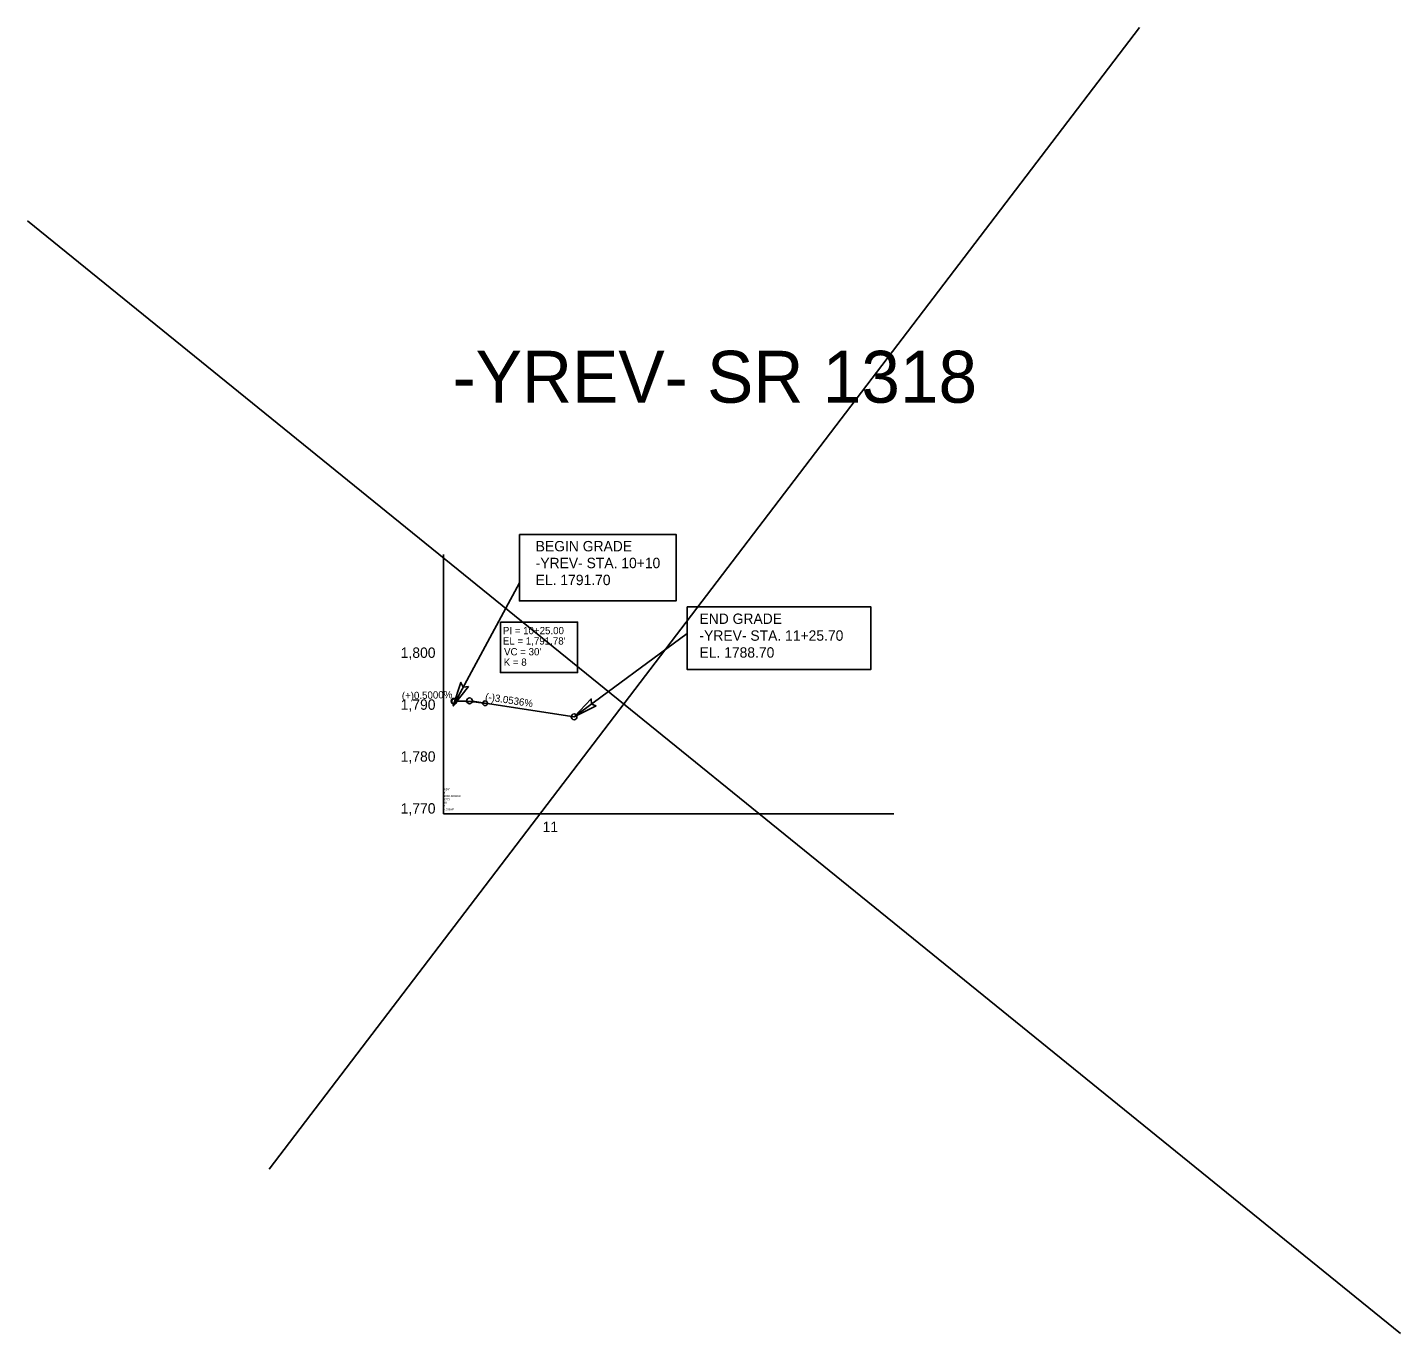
# Model space of a CAD drawing. Extents: x 572269 to 579912, y -56875 to -49627.
# Drawn here: x 578589 to 579912, y -53135 to -51877 of the extents above; entities that cross this region are included whole.
import ezdxf

# ---------------------------------------------------------------- set-up
doc = ezdxf.new("R2010")
doc.units = 0
for name, color, linetype in [('COGO Default Spiral', 7, 'Continuous'), ('Exist Profile Cell', 7, 'Continuous'), ('Exist Vertical Profile Ground Line', 7, 'Continuous'), ('Exist Vertical Profile Horizontal Axis Label Major', 7, 'Continuous'), ('Exist Vertical Profile Vertical Axis Label', 7, 'Continuous'), ('Prop Grid Mask', 7, 'Continuous'), ('Prop PFL Text', 7, 'Continuous'), ('Prop Vertical Profile Curve Label', 7, 'Continuous'), ('Prop Vertical Profile Grade', 7, 'Continuous'), ('Prop Vertical Profile Grade Label', 7, 'Continuous'), ('Prop VPI Label', 7, 'Continuous'), ('Typical Terminator CELL', 7, 'Continuous')]:
    doc.layers.add(name, color=color, linetype=linetype)

# ---------------------------------------------------------------- blocks, each defined once
blk = doc.blocks.new('TERMINATOR')
at = {"layer": 'Typical Terminator CELL'}
blk.add_lwpolyline([(-0.469, 0.081), (0, 0), (-0.471, -0.083), (-0.411, 0)], close=True, dxfattribs=at)

msp = doc.modelspace()

# ---------------------------------------------------------------- linework, layer by layer
at = {"layer": 'COGO Default Spiral'}
for p, q in [((579660.3, -51876.6), (578821.8, -52976.3)), ((578588.9, -52063), (579911.8, -53134.7))]:
    msp.add_line(p, q, dxfattribs=at)
at = {"layer": 'Exist Profile Cell'}
for q in [(578989.9, -52384.2), (579423.8, -52634.2), (578989.9, -52634.2)]:
    msp.add_line((578989.9, -52634.2), q, dxfattribs=at)
at = {"layer": 'Exist Vertical Profile Ground Line'}
msp.add_line((579029.9, -52527.6), (579115.6, -52540.7), dxfattribs=at)
msp.add_spline([(578999.9, -52525.7), (579000.5, -52525.6), (579001.1, -52525.6), (579001.7, -52525.6), (579002.3, -52525.6), (579002.9, -52525.6), (579003.5, -52525.6), (579004.1, -52525.6), (579004.7, -52525.6), (579005.3, -52525.6), (579005.9, -52525.6), (579006.5, -52525.6), (579007.1, -52525.6), (579007.7, -52525.6), (579008.3, -52525.7), (579008.9, -52525.7), (579009.5, -52525.7), (579010.1, -52525.7), (579010.7, -52525.7), (579011.3, -52525.8), (579011.9, -52525.8), (579012.5, -52525.8), (579013.1, -52525.8), (579013.7, -52525.9), (579014.3, -52525.9), (579014.9, -52525.9), (579015.5, -52526), (579016.1, -52526), (579016.7, -52526.1), (579017.3, -52526.1), (579017.9, -52526.2), (579018.5, -52526.2), (579019.1, -52526.3), (579019.7, -52526.3), (579020.3, -52526.4), (579020.9, -52526.4), (579021.5, -52526.5), (579022.1, -52526.6), (579022.7, -52526.6), (579023.3, -52526.7), (579023.9, -52526.8), (579024.5, -52526.8), (579025.1, -52526.9), (579025.7, -52527), (579026.3, -52527.1), (579026.9, -52527.1), (579027.5, -52527.2), (579028.1, -52527.3), (579028.7, -52527.4), (579029.3, -52527.5), (579029.9, -52527.6)], degree=3, dxfattribs=at)
at = {"layer": 'Prop Grid Mask'}
for points in [[(579062.9, -52364.9), (579213.9, -52364.9), (579213.9, -52429), (579062.9, -52429)], [(579224.7, -52434.6), (579401.4, -52434.6), (579401.4, -52495.2), (579224.7, -52495.2)], [(579044.6, -52449.4), (579119, -52449.4), (579119, -52498), (579044.6, -52498)]]:
    msp.add_lwpolyline(points, close=True, dxfattribs=at)
at = {"layer": 'Prop PFL Text'}
for p, q in [((578999.1, -52530.2), (579062.9, -52411.6)), ((579115.6, -52540.7), (579224.7, -52460.5))]:
    msp.add_line(p, q, dxfattribs=at)
at = {"layer": 'Prop Vertical Profile Curve Label'}
for centre in [(578999.9, -52525.7), (579029.9, -52527.6)]:
    msp.add_circle(centre, 2.25, dxfattribs=at)
at = {"layer": 'Prop Vertical Profile Grade'}
msp.add_line((579029.9, -52527.6), (579115.6, -52540.7), dxfattribs=at)
msp.add_spline([(578999.9, -52525.7), (579000.5, -52525.6), (579001.1, -52525.6), (579001.7, -52525.6), (579002.3, -52525.6), (579002.9, -52525.6), (579003.5, -52525.6), (579004.1, -52525.6), (579004.7, -52525.6), (579005.3, -52525.6), (579005.9, -52525.6), (579006.5, -52525.6), (579007.1, -52525.6), (579007.7, -52525.6), (579008.3, -52525.7), (579008.9, -52525.7), (579009.5, -52525.7), (579010.1, -52525.7), (579010.7, -52525.7), (579011.3, -52525.8), (579011.9, -52525.8), (579012.5, -52525.8), (579013.1, -52525.8), (579013.7, -52525.9), (579014.3, -52525.9), (579014.9, -52525.9), (579015.5, -52526), (579016.1, -52526), (579016.7, -52526.1), (579017.3, -52526.1), (579017.9, -52526.2), (579018.5, -52526.2), (579019.1, -52526.3), (579019.7, -52526.3), (579020.3, -52526.4), (579020.9, -52526.4), (579021.5, -52526.5), (579022.1, -52526.6), (579022.7, -52526.6), (579023.3, -52526.7), (579023.9, -52526.8), (579024.5, -52526.8), (579025.1, -52526.9), (579025.7, -52527), (579026.3, -52527.1), (579026.9, -52527.1), (579027.5, -52527.2), (579028.1, -52527.3), (579028.7, -52527.4), (579029.3, -52527.5), (579029.9, -52527.6)], degree=3, dxfattribs=at)
at = {"layer": 'Prop VPI Label'}
for p, q in [((578999.9, -52525.7), (579012.1, -52525.3)), ((579029.9, -52527.6), (579017.6, -52525.7))]:
    msp.add_line(p, q, dxfattribs=at)
for centre in [(578999.9, -52525.7), (579014.9, -52525.3), (579115.6, -52540.7)]:
    msp.add_circle(centre, 2.75, dxfattribs=at)

# ---------------------------------------------------------------- block references
at = {"layer": 'Prop PFL Text', "yscale": 49.99999999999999}
for p, xscale, rotation in [((578999.1, -52530.2), 49.999999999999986, -118.29550859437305), ((579115.6, -52540.7), 50, -143.96839720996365)]:
    msp.add_blockref('TERMINATOR', p, dxfattribs=dict(at, xscale=xscale, rotation=rotation))

# ---------------------------------------------------------------- texts
at = {"layer": 'Exist Profile Cell'}
for s, p in [('RDY', (578989.9, -52611.4)), ('Y', (578989.9, -52614.7)), ('1000.000000', (578989.9, -52617.9)), ('1770', (578989.9, -52621.2)), ('10', (578989.9, -52624.4)), ('2', (578989.9, -52627.7)), ('NOGAP', (578989.9, -52630.9))]:
    msp.add_text(s, height=2, dxfattribs=at).set_placement(p)
at = {"layer": 'Exist Vertical Profile Horizontal Axis Label Major'}
msp.add_text('11', height=10, dxfattribs=at).set_placement((579085.3, -52651.7))
at = {"layer": 'Exist Vertical Profile Vertical Axis Label'}
for s, p in [('1,800', (578948.6, -52483.9)), ('1,790', (578948.6, -52533.9)), ('1,780', (578948.6, -52583.9)), ('1,770', (578948.6, -52633.9))]:
    msp.add_text(s, height=10, dxfattribs=at).set_placement(p)
at = {"layer": 'Prop PFL Text'}
for s, height, p in [('-YREV- SR 1318', 50, (578998.5, -52238.1)), ('BEGIN GRADE ', 10, (579078.6, -52381.3)), ('-YREV- STA. 10+10', 10, (579078.6, -52397.5)), ('EL. 1791.70', 10, (579078.6, -52413.8)), ('END GRADE ', 10, (579236.4, -52451.2)), ('-YREV- STA. 11+25.70 ', 10, (579236.4, -52467.4)), ('EL. 1788.70', 10, (579236.4, -52483.7))]:
    msp.add_text(s, height=height, dxfattribs=at).set_placement(p)
at = {"layer": 'Prop Vertical Profile Curve Label'}
for s, p in [("VC = 30'", (579048.1, -52481.5)), ('K = 8', (579047.8, -52491.5))]:
    msp.add_text(s, height=7, dxfattribs=at).set_placement(p)
at = {"layer": 'Prop Vertical Profile Grade Label'}
for s, rotation, p in [('(+)0.5000%', 1.4321, (578949.7, -52523.9)), ('(-)3.0536%', 351.3191, (579029.6, -52524.5))]:
    msp.add_text(s, height=7, rotation=rotation, dxfattribs=at).set_placement(p)
at = {"layer": 'Prop VPI Label'}
for s, p in [('PI = 10+25.00', (579047, -52461.1)), ("EL = 1,791.78'", (579047, -52471.1))]:
    msp.add_text(s, height=7, dxfattribs=at).set_placement(p)

doc.saveas('drawing.dxf')
